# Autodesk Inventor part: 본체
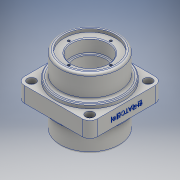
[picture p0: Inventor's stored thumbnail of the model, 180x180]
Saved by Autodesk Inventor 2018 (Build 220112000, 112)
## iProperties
Created: 2023-10
Part Number: 본체
Material: 알루미늄 6061
Document SubType Name: Modeling
Designer: home
Density: 2.7 g/cm^3
Appearance: 알루미늄 - 평지
Mass: 945.786 g
Surface Area: 536.974 cm^2
Volume: 350.291 cm^3
Author: home
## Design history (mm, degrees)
sketch "스케치1"
  geometry: L1 (-37, 47)-(37, 47); L2 (47, 37)-(47, -37); L3 (37, -47)-(-37, -47); L4 (-47, -37)-(-47, 37); A1 r 10 centre (-37, 37) between (-37, 47) and (-47, 37); A2 r 10 centre (37, 37) between (47, 37) and (37, 47); A3 r 10 centre (37, -37) between (37, -47) and (47, -37); A4 r 10 centre (-37, -37) between (-47, -37) and (-37, -47); 4 further points
  constraints: 8 end point, 8 point on circle, 8 tangent, 6 point on line, 4 centre point, 3 equal radius, 2 parallel, 1 horizontal, 1 perpendicular
  dimensions: "d0" = 94 distance of point (47, -47) point (-47, -47); "d1" = 94 distance of point (47, 47) point (47, -47); "d2" = 47 distance from line of point (0, 0) L1; "d3" = 47 distance from line of point (0, 0) L4; "d4" = 10 radius of A1
extrude "돌출1" new body sketch "스케치1" stored distance "d5" = 20; taper "d6" = 0 deg
sketch "스케치2"
  geometry: C1 r 38 at (0, 0); 1 further point
  constraints: 1 centre point, 1 coincident
  dimensions: "d7" = 76 diameter of C1
extrude "돌출2" join sketch "스케치2" stored distance "d8" = 90; taper "d9" = 0 deg
sketch "스케치3"
  geometry: C1 r 44 at (0, 0); 1 further point
  constraints: 1 centre point, 1 coincident
  dimensions: "d10" = 88 diameter of C1
extrude "돌출3" join sketch "스케치3" stored distance "d11" = 30; taper "d12" = 0 deg
sketch "스케치4"
  geometry: C1 r 33 at (0, 0); 1 further point
  constraints: 1 centre point, 1 coincident
  dimensions: "d13" = 66 diameter of C1
extrude "돌출4" cut sketch "스케치4" distance "d14" = 4; taper "d15" = 0 deg
sketch "스케치5"
  geometry: C1 r 23.5 at (0, 0); 1 further point
  constraints: 1 centre point, 1 coincident
  dimensions: "d16" = 47 diameter of C1
extrude "돌출5" cut sketch "스케치5" distance "d17" = 17; taper "d18" = 0 deg
sketch "스케치6"
  geometry: C1 r 20.5 at (0, 0); 1 further point
  constraints: 1 centre point, 1 coincident
  dimensions: "d19" = 41 diameter of C1
extrude "돌출6" cut sketch "스케치6" extent not by distance; stored distance "d20" = 17; taper "d21" = 0 deg
chamfer "모따기1" distance "d22" = 1; stored, may be unused: second distance "d23" = 2, angle "d24" = 45 deg
fillet "모깎기1" dims "d25" = 1
sketch "스케치7" dims "d26" = 54
  geometry: 3 further points
  constraints: 2 vertical alignment, 1 coincident, 2 other
hole "구멍1" sketch "스케치7" at (0, 27) diameter "d27" = 3.242; stored, may be unused: countersink angle "d31" = 90 deg, drill point angle "d33" = 118 deg; dims "d28" = 8, "d29" = 4, "d30" = 2, "d32" = 10
sketch "스케치8"
  geometry: L1 (0, 0)-(-53, 0); L2 (0, 0)-(-37.477, 37.477); C1 r 5.5 at (-37.477, 37.477); A1 r 53 centre (0, 0) between (-53, 0) and (-37.477, 37.477); 1 further point
  constraints: 4 end point, 2 centre point, 2 coincident, 2 point on circle, 1 horizontal
  dimensions: "d37" = 106 diameter of A1; "d38" = 45 deg angle of L1 L2; "d39" = 11 diameter of C1
extrude "돌출7" cut sketch "스케치8" distance "d40" = 7; taper "d41" = 0 deg
sketch "스케치9"
  geometry: C1 r 3.3 at (0, 0); 1 further point
  constraints: 1 centre point
  dimensions: "d42" = 6.6 diameter of C1; "d43" = 37.47666 horizontal distance of point (37.477, -37.477) C1.centre; "d44" = 37.47666 horizontal distance of point (37.477, -37.477) C1.centre
extrude "돌출8" cut sketch "스케치9" extent not by distance; stored distance "d45" = 7; taper "d46" = 0 deg
sketch "스케치10"
  geometry: C1 r 7 at (37, 10); 1 further point
  constraints: 1 centre point, 1 coincident
  dimensions: "d47" = 14 diameter of C1
extrude "돌출9" cut sketch "스케치10" distance "d48" = 2; taper "d49" = 0 deg
sketch "스케치11"
  geometry: C1 r 3.5 at (0, 0); 1 further point
  constraints: 1 centre point, 1 coincident
  dimensions: "d50" = 7 diameter of C1
extrude "돌출10" cut sketch "스케치11" distance "d51" = 2; taper "d52" = 0 deg
sketch "스케치12"
  geometry: 2 further points
  constraints: 1 coincident
hole "구멍2" sketch "스케치12" at (0, 0) diameter "d53" = 5.188; stored, may be unused: countersink angle "d57" = 90 deg, drill point angle "d59" = 118 deg; dims "d54" = 12, "d55" = 11, "d56" = 7, "d58" = 50
sketch "스케치13"
  geometry: 2 further points
  constraints: 1 coincident, 1 other
feature "엠보싱1" sketch "스케치13" dims "d0" = 94, "d1" = 94, "d2" = 47, "d3" = 47, "d4" = 10, "d60" = 0.5, "d61" = 0
fillet "모깎기2" dims "d62" = 3
chamfer "모따기2" distance "d63" = 1; stored, may be unused: second distance "d64" = 2, angle "d65" = 45 deg
node "솔리드1"
mirror "미러1"
pattern_circular "원형 패턴1" dims angle "d35" = 360 deg
mirror "미러2"
mirror "미러3"
mirror "미러4"
mirror "미러5"
